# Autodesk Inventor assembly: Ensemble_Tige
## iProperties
Shininess: 64.0
Length Units: 11269
Angle Units: 11279
Time Units: 11290
Mass Units: 11283
Length Display Precision: 3
Angle Display Precision: 2
Compacted: True
Created: 2004-05
Part Number: Ensemble_Tige
Document SubType Name: Assembly
Designer: David
Density: 0.0
Volumn: 0.0
Area: 0.0
PropertySet Name: Model Information
Control State: 0
Master: False
Checked Out: False
Author: David
